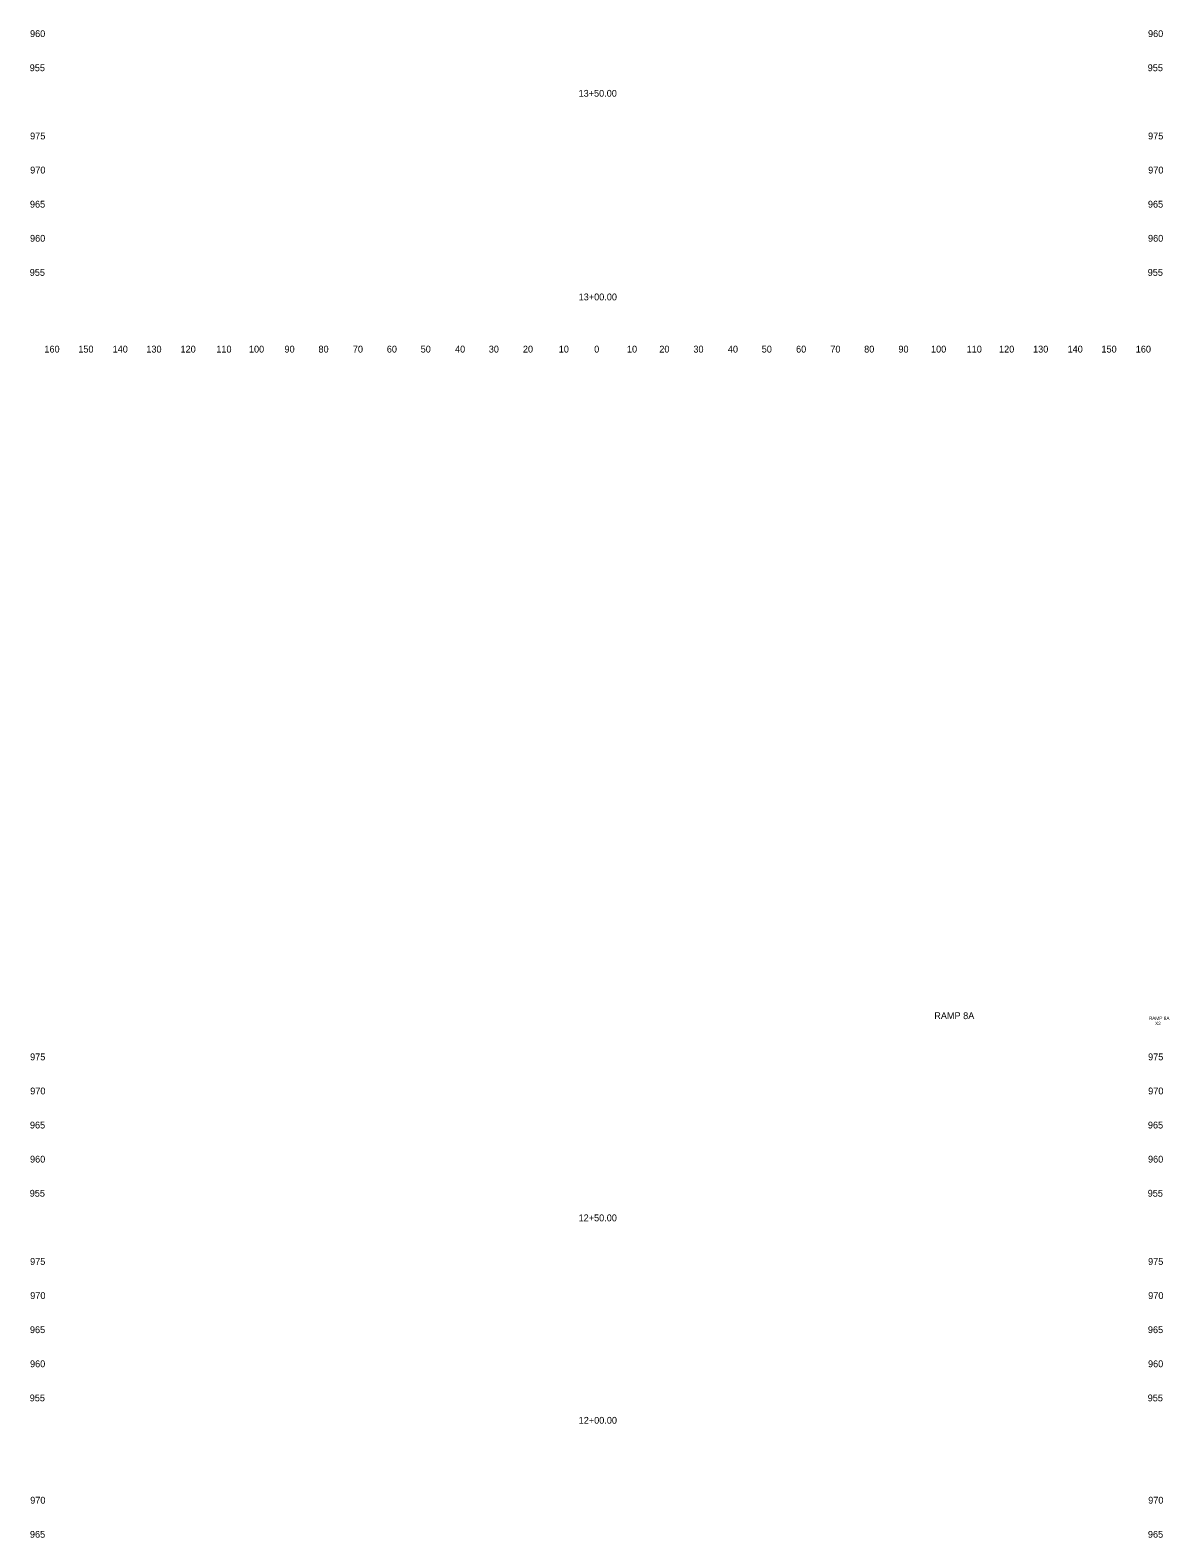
# Model space of a CAD drawing. Extents: x 4994 to 5328, y 4997 to 8804.
# Drawn here: x 4993.9 to 5327.8, y 5450 to 5892 of the extents above; entities that cross this region are included whole.
import ezdxf

# ---------------------------------------------------------------- set-up
doc = ezdxf.new("R2010")
doc.units = 0
for name, color, linetype in [('RD_SHT_ID', 7, 'Continuous'), ('RD_XS_TX_Offset', 7, 'Continuous'), ('RD_XS_TX_Station', 7, 'Continuous')]:
    doc.layers.add(name, color=color, linetype=linetype)

msp = doc.modelspace()

# ---------------------------------------------------------------- texts
at = {"layer": 'RD_SHT_ID'}
for s, height, p in [('RAMP 8A', 2, (5259.02, 5602.06)), ('RAMP 8A', 1, (5321.93, 5601.8)), ('X2', 1, (5323.74, 5600.3))]:
    msp.add_text(s, height=height, dxfattribs=at).set_placement(p)
at = {"layer": 'RD_XS_TX_Offset'}
for s, p in [('960', (4993.89, 5890)), ('960', (5321.69, 5890)), ('955', (4993.8, 5880)), ('955', (5321.6, 5880)), ('975', (4993.91, 5860)), ('975', (5321.71, 5860)), ('970', (4993.94, 5850)), ('970', (5321.74, 5850)), ('965', (4993.86, 5840)), ('965', (5321.66, 5840)), ('960', (4993.89, 5830)), ('960', (5321.69, 5830)), ('955', (4993.8, 5820)), ('955', (5321.6, 5820)), ('160', (4998.1, 5797.5)), ('150', (5008.04, 5797.5)), ('140', (5018.1, 5797.5)), ('130', (5027.99, 5797.5)), ('120', (5038.01, 5797.5)), ('110', (5048.51, 5797.5)), ('100', (5058.07, 5797.5)), ('90', (5068.5, 5797.5)), ('80', (5078.46, 5797.5)), ('70', (5088.54, 5797.5)), ('60', (5098.5, 5797.5)), ('50', (5108.43, 5797.5)), ('40', (5118.5, 5797.5)), ('30', (5128.39, 5797.5)), ('20', (5138.4, 5797.5)), ('10', (5148.91, 5797.5)), ('0', (5159.3, 5797.5)), ('0', (5159.3, 5797.5)), ('10', (5168.91, 5797.5)), ('20', (5178.4, 5797.5)), ('30', (5188.39, 5797.5)), ('40', (5198.5, 5797.5)), ('50', (5208.43, 5797.5)), ('60', (5218.5, 5797.5)), ('70', (5228.54, 5797.5)), ('80', (5238.46, 5797.5)), ('90', (5248.5, 5797.5)), ('100', (5258.07, 5797.5)), ('110', (5268.51, 5797.5)), ('120', (5278.01, 5797.5)), ('130', (5287.99, 5797.5)), ('140', (5298.1, 5797.5)), ('150', (5308.04, 5797.5)), ('160', (5318.1, 5797.5)), ('975', (4993.91, 5590)), ('975', (5321.71, 5590)), ('970', (4993.94, 5580)), ('970', (5321.74, 5580)), ('965', (4993.86, 5570)), ('965', (5321.66, 5570)), ('960', (4993.89, 5560)), ('960', (5321.69, 5560)), ('955', (4993.8, 5550)), ('955', (5321.6, 5550)), ('975', (4993.91, 5530)), ('975', (5321.71, 5530)), ('970', (4993.94, 5520)), ('970', (5321.74, 5520)), ('965', (4993.86, 5510)), ('965', (5321.66, 5510)), ('960', (4993.89, 5500)), ('960', (5321.69, 5500)), ('955', (4993.8, 5490)), ('955', (5321.6, 5490)), ('970', (4993.94, 5460)), ('970', (5321.74, 5460)), ('965', (4993.86, 5450)), ('965', (5321.66, 5450))]:
    msp.add_text(s, height=2, dxfattribs=at).set_placement(p)
at = {"layer": 'RD_XS_TX_Station'}
for s, p in [('13+50.00', (5154.72, 5872.51)), ('13+00.00', (5154.75, 5812.81)), ('12+50.00', (5154.73, 5542.79)), ('12+00.00', (5154.76, 5483.43))]:
    msp.add_text(s, height=2, dxfattribs=at).set_placement(p)

doc.saveas('drawing.dxf')
